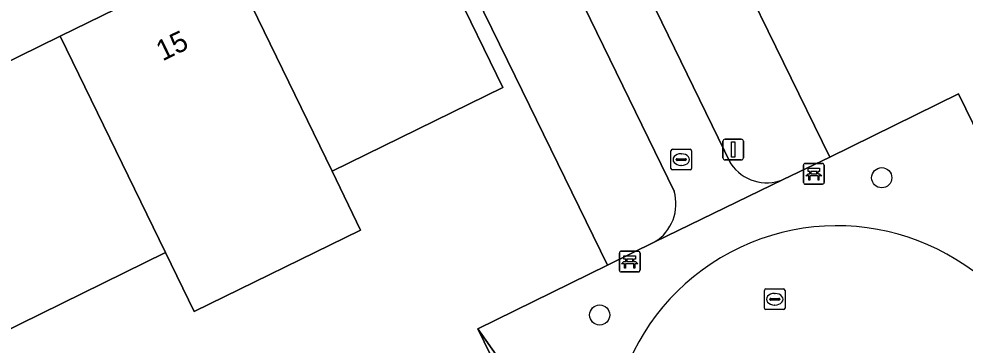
# Model space of a CAD drawing. Extents: x 160455 to 162082, y 388339 to 389736.
# Drawn here: x 160797.83 to 160843.76, y 388820.05 to 388835.85 of the extents above; entities that cross this region are included whole.
import ezdxf

# ---------------------------------------------------------------- set-up
doc = ezdxf.new("R2010")
doc.units = 0
for name, color, linetype in [('IMGEO_Bank', 7, 'Continuous'), ('IMGEO_Berm_groen', 7, 'Continuous'), ('IMGEO_Boom', 7, 'Continuous'), ('IMGEO_Erf', 7, 'Continuous'), ('IMGEO_Lichtmast', 7, 'Continuous'), ('IMGEO_Muur', 7, 'Continuous'), ('IMGEO_Pand', 7, 'Continuous'), ('IMGEO_Pand_nummerreeks', 7, 'Continuous'), ('IMGEO_Rijbaan_lokaal_open', 7, 'Continuous'), ('IMGEO_Rioolput', 7, 'Continuous'), ('IMGEO_Voetpad_open', 7, 'Continuous')]:
    doc.layers.add(name, color=color, linetype=linetype)

msp = doc.modelspace()

# ---------------------------------------------------------------- linework, layer by layer
at = {"layer": 'IMGEO_Bank'}
for p, q in [((160835.992, 388828.848), (160836.833, 388828.848)), ((160836.833, 388828.848), (160835.992, 388828.848)), ((160835.917, 388827.923), (160835.917, 388828.764)), ((160835.917, 388828.764), (160835.917, 388827.923)), ((160836.226, 388828.354), (160836.226, 388828.46)), ((160836.27, 388828.46), (160836.27, 388828.354)), ((160836.558, 388828.466), (160836.276, 388828.466)), ((160836.564, 388828.354), (160836.564, 388828.46)), ((160836.608, 388828.46), (160836.608, 388828.354)), ((160836.917, 388828.773), (160836.917, 388827.932)), ((160836.917, 388827.932), (160836.917, 388828.773)), ((160836.614, 388828.246), (160836.221, 388828.246)), ((160836.276, 388828.348), (160836.558, 388828.348)), ((160836.842, 388827.848), (160836.001, 388827.848)), ((160836.001, 388827.848), (160836.842, 388827.848)), ((160826.977, 388823.667), (160826.977, 388824.508)), ((160826.977, 388824.508), (160826.977, 388823.667)), ((160827.052, 388824.592), (160827.893, 388824.592)), ((160827.893, 388824.592), (160827.052, 388824.592)), ((160827.977, 388824.517), (160827.977, 388823.676)), ((160827.977, 388823.676), (160827.977, 388824.517)), ((160827.674, 388823.99), (160827.281, 388823.99)), ((160827.286, 388824.098), (160827.286, 388824.204)), ((160827.33, 388824.204), (160827.33, 388824.098)), ((160827.618, 388824.21), (160827.336, 388824.21)), ((160827.336, 388824.092), (160827.618, 388824.092)), ((160827.624, 388824.098), (160827.624, 388824.204)), ((160827.668, 388824.204), (160827.668, 388824.098)), ((160827.902, 388823.592), (160827.061, 388823.592)), ((160827.061, 388823.592), (160827.902, 388823.592))]:
    msp.add_line(p, q, dxfattribs=at)
for points in [[(160836.22, 388828.466), (160836.134, 388828.466), (160836.134, 388828.627), (160836.697, 388828.627), (160836.697, 388828.466), (160836.614, 388828.466)], [(160836.164, 388828.246), (160836.022, 388828.246), (160836.134, 388828.348), (160836.22, 388828.348)], [(160836.214, 388828.239), (160836.214, 388828.032), (160836.171, 388828.032), (160836.171, 388828.239)], [(160836.614, 388828.348), (160836.697, 388828.348), (160836.809, 388828.246), (160836.67, 388828.246)], [(160836.664, 388828.239), (160836.664, 388828.032), (160836.62, 388828.032), (160836.62, 388828.239)], [(160827.28, 388824.21), (160827.194, 388824.21), (160827.194, 388824.371), (160827.757, 388824.371), (160827.757, 388824.21), (160827.674, 388824.21)], [(160827.224, 388823.99), (160827.082, 388823.99), (160827.194, 388824.092), (160827.28, 388824.092)], [(160827.274, 388823.983), (160827.274, 388823.776), (160827.231, 388823.776), (160827.231, 388823.983)], [(160827.674, 388824.092), (160827.757, 388824.092), (160827.869, 388823.99), (160827.73, 388823.99)], [(160827.724, 388823.983), (160827.724, 388823.776), (160827.68, 388823.776), (160827.68, 388823.983)]]:
    msp.add_lwpolyline(points, dxfattribs=at)
for centre, radius, start, end in [((160835.995, 388828.77), 0.0779, 92.4484, 184.2845), ((160835.995, 388828.77), 0.0779, 92.4484, 184.2845), ((160836.839, 388828.77), 0.0779, 2.4484, 94.2845), ((160836.839, 388828.77), 0.0779, 2.4484, 94.2845), ((160836.219, 388828.459), 0.00671, 2.8957, 87.1043), ((160836.276, 388828.459), 0.00671, 92.8957, 177.1043), ((160836.558, 388828.459), 0.00671, 2.8957, 87.1043), ((160836.615, 388828.459), 0.00671, 92.8957, 177.1043), ((160836.164, 388828.239), 0.00671, 2.8957, 87.1043), ((160836.221, 388828.239), 0.00671, 92.8957, 177.1043), ((160836.219, 388828.355), 0.00671, 272.8957, 357.1043), ((160836.276, 388828.355), 0.00671, 182.8957, 267.1043), ((160836.558, 388828.355), 0.00671, 272.8957, 357.1043), ((160836.615, 388828.355), 0.00671, 182.8957, 267.1043), ((160836.613, 388828.239), 0.00671, 2.8957, 87.1043), ((160836.67, 388828.239), 0.00671, 92.8957, 177.1043), ((160836.839, 388827.926), 0.0779, 272.4484, 4.2845), ((160836.839, 388827.926), 0.0779, 272.4484, 4.2845), ((160835.995, 388827.926), 0.0779, 182.4484, 274.2845), ((160835.995, 388827.926), 0.0779, 182.4484, 274.2845), ((160827.055, 388824.514), 0.0779, 92.4484, 184.2845), ((160827.055, 388824.514), 0.0779, 92.4484, 184.2845), ((160827.899, 388824.514), 0.0779, 2.4484, 94.2845), ((160827.899, 388824.514), 0.0779, 2.4484, 94.2845), ((160827.224, 388823.983), 0.00671, 2.8957, 87.1043), ((160827.281, 388823.983), 0.00671, 92.8957, 177.1043), ((160827.279, 388824.203), 0.00671, 2.8957, 87.1043), ((160827.279, 388824.099), 0.00671, 272.8957, 357.1043), ((160827.336, 388824.203), 0.00671, 92.8957, 177.1043), ((160827.336, 388824.099), 0.00671, 182.8957, 267.1043), ((160827.618, 388824.203), 0.00671, 2.8957, 87.1043), ((160827.618, 388824.099), 0.00671, 272.8957, 357.1043), ((160827.675, 388824.203), 0.00671, 92.8957, 177.1043), ((160827.675, 388824.099), 0.00671, 182.8957, 267.1043), ((160827.673, 388823.983), 0.00671, 2.8957, 87.1043), ((160827.73, 388823.983), 0.00671, 92.8957, 177.1043), ((160827.055, 388823.67), 0.0779, 182.4484, 274.2845), ((160827.055, 388823.67), 0.0779, 182.4484, 274.2845), ((160827.899, 388823.67), 0.0779, 272.4484, 4.2845), ((160827.899, 388823.67), 0.0779, 272.4484, 4.2845)]:
    msp.add_arc(centre, radius, start, end, dxfattribs=at)
at = {"layer": 'IMGEO_Berm_groen'}
for points in [[(160825.107, 388853.891), (160821.137, 388851.908), (160832.392, 388828.839)], [(160834.925, 388828.065), (160837.199, 388829.157), (160832.7, 388838.342), (160825.107, 388853.891)], [(160818.384, 388850.563), (160814.32, 388848.575), (160821.923, 388833.073), (160826.4, 388823.92), (160828.689, 388825.043)], [(160829.631, 388827.513), (160818.384, 388850.563)]]:
    msp.add_lwpolyline(points, dxfattribs=at)
for centre, radius, start, end in [((160834.13, 388829.996), 2.088, 213.6448, 292.3724), ((160827.558, 388826.889), 2.165, 301.4923, 16.7564)]:
    msp.add_arc(centre, radius, start, end, dxfattribs=at)
at = {"layer": 'IMGEO_Boom'}
for centre in [(160839.712, 388828.158), (160826.02, 388821.505)]:
    msp.add_circle(centre, 0.489, dxfattribs=at)
at = {"layer": 'IMGEO_Erf'}
for points in [[(160876.34, 388878.995), (160869.603, 388875.706), (160825.107, 388853.891), (160832.7, 388838.342), (160837.199, 388829.157), (160843.446, 388832.228), (160866.085, 388785.973), (160863.24, 388784.572), (160868.516, 388773.685), (160872.989, 388774.58)], [(160820.108, 388820.831), (160826.4, 388823.92), (160821.923, 388833.073), (160814.32, 388848.575), (160763.253, 388823.601), (160763.353, 388823.428)], [(160816.37, 388842.689), (160821.325, 388832.529), (160813.027, 388828.476), (160814.416, 388825.619), (160806.337, 388821.673), (160804.945, 388824.528), (160796.865, 388820.581), (160788.782, 388816.633), (160788.522, 388816.506), (160789.919, 388813.654), (160784.638, 388811.066), (160782.283, 388811.818), (160781.635, 388813.142), (160780.692, 388812.681), (160776.912, 388810.835), (160772.422, 388808.635), (160767.438, 388818.809), (160767.329, 388818.751), (160767.172, 388819.067), (160775.574, 388823.171), (160783.66, 388827.12), (160791.746, 388831.069), (160799.832, 388835.019), (160807.926, 388838.972)], [(160842.711, 388774.525), (160820.108, 388820.831)]]:
    msp.add_lwpolyline(points, dxfattribs=at)
at = {"layer": 'IMGEO_Lichtmast'}
for p, q in [((160832.004, 388829.123), (160832.004, 388829.923)), ((160832.004, 388829.923), (160832.004, 388829.123)), ((160832.104, 388830.023), (160832.894, 388830.023)), ((160832.894, 388830.023), (160832.104, 388830.023)), ((160832.994, 388829.923), (160832.994, 388829.123)), ((160832.994, 388829.123), (160832.994, 388829.923)), ((160832.894, 388829.023), (160832.104, 388829.023)), ((160832.104, 388829.023), (160832.894, 388829.023))]:
    msp.add_line(p, q, dxfattribs=at)
msp.add_lwpolyline([(160832.424, 388829.898), (160832.574, 388829.898), (160832.574, 388829.148), (160832.424, 388829.148), (160832.424, 388829.898)], dxfattribs=at)
for centre, start, end in [((160832.104, 388829.923), 90, 180), ((160832.104, 388829.923), 90, 180), ((160832.894, 388829.923), 0, 90), ((160832.894, 388829.923), 360, 90), ((160832.104, 388829.123), 180, 270), ((160832.104, 388829.123), 180, 270), ((160832.894, 388829.123), 270, 0), ((160832.894, 388829.123), 270, 0)]:
    msp.add_arc(centre, 0.1, start, end, dxfattribs=at)
at = {"layer": 'IMGEO_Muur'}
msp.add_lwpolyline([(160820.108, 388820.831), (160826.4, 388823.92)], dxfattribs=at)
at = {"layer": 'IMGEO_Pand'}
for points in [[(160813.027, 388828.476), (160821.325, 388832.529), (160816.37, 388842.689), (160816.478, 388842.742), (160816.305, 388843.064), (160807.926, 388838.972)], [(160807.926, 388838.972), (160799.832, 388835.019), (160804.945, 388824.528), (160806.337, 388821.673), (160814.416, 388825.619), (160813.027, 388828.476)], [(160804.945, 388824.528), (160799.832, 388835.019), (160791.746, 388831.069), (160796.865, 388820.581)]]:
    msp.add_lwpolyline(points, close=True, dxfattribs=at)
at = {"layer": 'IMGEO_Rijbaan_lokaal_open'}
for points in [[(160821.137, 388851.908), (160818.384, 388850.563), (160829.631, 388827.513)], [(160832.392, 388828.839), (160821.137, 388851.908)], [(160828.689, 388825.043), (160834.925, 388828.065)]]:
    msp.add_lwpolyline(points, dxfattribs=at)
for centre, radius, start, end in [((160834.13, 388829.996), 2.088, 213.6448, 292.3724), ((160827.558, 388826.889), 2.165, 301.4923, 16.7564), ((160837.543, 388814.784), 11.045, 28.3713, 202.0169)]:
    msp.add_arc(centre, radius, start, end, dxfattribs=at)
at = {"layer": 'IMGEO_Rioolput'}
for p, q in [((160829.481, 388828.612), (160829.481, 388829.464)), ((160829.556, 388829.538), (160830.408, 388829.538)), ((160829.969, 388829.318), (160829.994, 388829.318)), ((160830.482, 388829.464), (160830.482, 388828.612)), ((160829.74, 388829.032), (160829.74, 388829.044)), ((160830.178, 388828.995), (160829.78, 388828.995)), ((160829.783, 388829.081), (160830.181, 388829.081)), ((160830.224, 388829.044), (160830.224, 388829.032)), ((160830.408, 388828.538), (160829.556, 388828.538)), ((160829.992, 388828.758), (160829.967, 388828.758)), ((160834.019, 388821.842), (160834.019, 388822.694)), ((160834.094, 388822.768), (160834.946, 388822.768)), ((160834.507, 388822.548), (160834.532, 388822.548)), ((160835.02, 388822.694), (160835.02, 388821.842)), ((160834.278, 388822.262), (160834.278, 388822.274)), ((160834.716, 388822.225), (160834.318, 388822.225)), ((160834.321, 388822.311), (160834.719, 388822.311)), ((160834.53, 388821.988), (160834.505, 388821.988)), ((160834.762, 388822.274), (160834.762, 388822.262)), ((160834.946, 388821.768), (160834.094, 388821.768))]:
    msp.add_line(p, q, dxfattribs=at)
for points in [[(160829.481, 388828.612), (160829.481, 388829.464)], [(160829.556, 388829.538), (160830.408, 388829.538)], [(160830.482, 388829.464), (160830.482, 388828.612)], [(160830.408, 388828.538), (160829.556, 388828.538)], [(160834.019, 388821.842), (160834.019, 388822.694)], [(160834.094, 388822.768), (160834.946, 388822.768)], [(160835.02, 388822.694), (160835.02, 388821.842)], [(160834.946, 388821.768), (160834.094, 388821.768)]]:
    msp.add_lwpolyline(points, dxfattribs=at)
for centre, radius, start, end in [((160829.558, 388829.462), 0.0765, 91.552, 178.448), ((160829.558, 388829.462), 0.0765, 91.552, 178.448), ((160830.406, 388829.462), 0.0765, 1.552, 88.448), ((160830.406, 388829.462), 0.0765, 1.552, 88.448), ((160829.78, 388829.041), 0.0403, 85.8775, 175.7526), ((160829.777, 388829.031), 0.0366, 178.938, 274.7102), ((160830.181, 388829.038), 0.043, 264.8664, 352.4533), ((160830.185, 388829.043), 0.0386, 1.7309, 96.639), ((160829.558, 388828.614), 0.0765, 181.552, 268.448), ((160829.558, 388828.614), 0.0765, 181.552, 268.448), ((160830.406, 388828.614), 0.0765, 271.552, 358.448), ((160830.406, 388828.614), 0.0765, 271.552, 358.448), ((160834.096, 388822.692), 0.0765, 91.552, 178.448), ((160834.096, 388822.692), 0.0765, 91.552, 178.448), ((160834.944, 388822.692), 0.0765, 1.552, 88.448), ((160834.944, 388822.692), 0.0765, 1.552, 88.448), ((160834.318, 388822.271), 0.0403, 85.8775, 175.7526), ((160834.315, 388822.261), 0.0366, 178.938, 274.7102), ((160834.719, 388822.268), 0.043, 264.8664, 352.4533), ((160834.723, 388822.273), 0.0386, 1.7309, 96.639), ((160834.096, 388821.844), 0.0765, 181.552, 268.448), ((160834.096, 388821.844), 0.0765, 181.552, 268.448), ((160834.944, 388821.844), 0.0765, 271.552, 358.448), ((160834.944, 388821.844), 0.0765, 271.552, 358.448)]:
    msp.add_arc(centre, radius, start, end, dxfattribs=at)
for centre, major_axis, ratio, start_param, end_param in [((160829.968, 388829.038), (-0.387, 0.002), 0.722429, 4.712389, 7.853982), ((160829.993, 388829.038), (-0.39, 0.002), 0.717154, 1.570796, 4.712389), ((160834.506, 388822.268), (-0.387, 0.002), 0.722429, 4.712389, 7.853982), ((160834.531, 388822.268), (-0.39, 0.002), 0.717154, 1.570796, 4.712389)]:
    msp.add_ellipse(centre, major_axis=major_axis, ratio=ratio, start_param=start_param, end_param=end_param, dxfattribs=at)
at = {"layer": 'IMGEO_Voetpad_open'}
for points in [[(160868.516, 388773.685), (160863.24, 388784.572), (160866.085, 388785.973), (160843.446, 388832.228), (160837.199, 388829.157), (160834.925, 388828.065), (160828.689, 388825.043), (160826.4, 388823.92), (160820.108, 388820.831), (160827.303, 388810.643)], [(160839.036, 388786.566), (160828.271, 388808.613), (160827.303, 388810.643), (160820.108, 388820.831), (160842.711, 388774.525), (160845.592, 388775.926), (160850.954, 388765.091), (160855.423, 388755.962), (160855.915, 388754.895)]]:
    msp.add_lwpolyline(points, dxfattribs=at)
msp.add_arc((160837.543, 388814.784), 11.045, 28.3713, 202.0169, dxfattribs=at)

# ---------------------------------------------------------------- texts
at = {"layer": 'IMGEO_Pand_nummerreeks'}
msp.add_text('15', height=1, rotation=26.0295, dxfattribs=at).set_placement((160804.8, 388833.794))

doc.saveas('drawing.dxf')
